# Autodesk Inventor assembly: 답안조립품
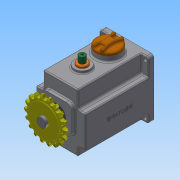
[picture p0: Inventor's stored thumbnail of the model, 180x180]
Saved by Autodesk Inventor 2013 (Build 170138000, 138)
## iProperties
Created: 2017-12
Part Number: 답안조립품
Document SubType Name: Assembly
Designer: Administrator
Author: Administrator
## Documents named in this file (17)
- C:\Users\Administrator\Desktop\371208V1018\답안조립품.iam
- C:\Users\Administrator\Desktop\371208V1018\본체.ipt
- C:\Users\Administrator\Desktop\371208V1018\멈춤나사 M3x8.ipt
- C:\Users\Administrator\Desktop\371208V1018\메인축.ipt
- C:\Users\Administrator\Desktop\371208V1018\베어링 608.ipt
- C:\Users\Administrator\Desktop\371208V1018\베어링 6003.ipt
- C:\Users\Administrator\Desktop\371208V1018\볼트 M4 x 10.ipt
- C:\Users\Administrator\Desktop\371208V1018\부시.ipt
- C:\Users\Administrator\Desktop\371208V1018\상부 캡.ipt
- C:\Users\Administrator\Desktop\371208V1018\서브축.ipt
- C:\Users\Administrator\Desktop\371208V1018\스프로킷.ipt
- C:\Users\Administrator\Desktop\371208V1018\슬라이더.ipt
- C:\Users\Administrator\Desktop\371208V1018\오일 실 8 22 7.ipt
- C:\Users\Administrator\Desktop\371208V1018\오일 실 17 32 8.ipt
- C:\Users\Administrator\Desktop\371208V1018\커버.ipt
- C:\Users\Administrator\Desktop\371208V1018\키 5 x 5 x 18.ipt
- C:\Users\Administrator\Desktop\371208V1018\가변스프링.ipt
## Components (1 placed, 1 different names)
1. 가변스프링:1
